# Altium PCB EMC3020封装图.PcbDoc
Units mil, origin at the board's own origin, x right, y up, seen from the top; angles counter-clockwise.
Board outline 6000 x 4000 mil, 2 copper layers (顶面, 底面), stack 12.7 mil thick; 1 components, 0 nets, 27 pads, 0 vias.
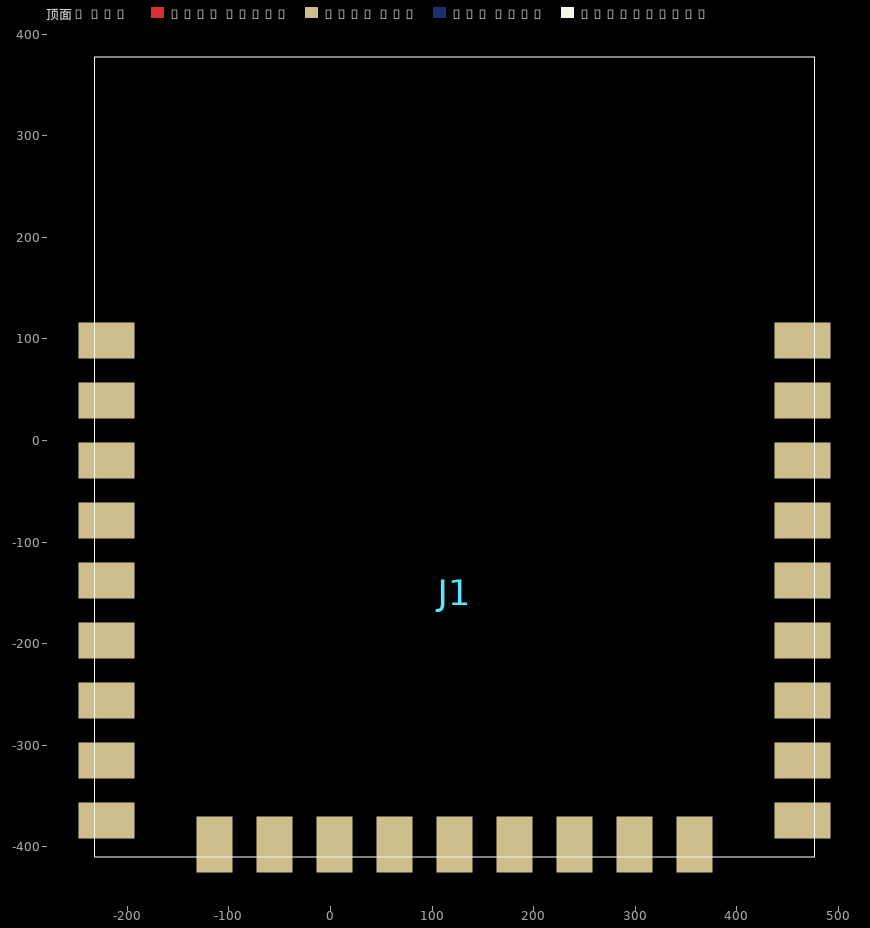
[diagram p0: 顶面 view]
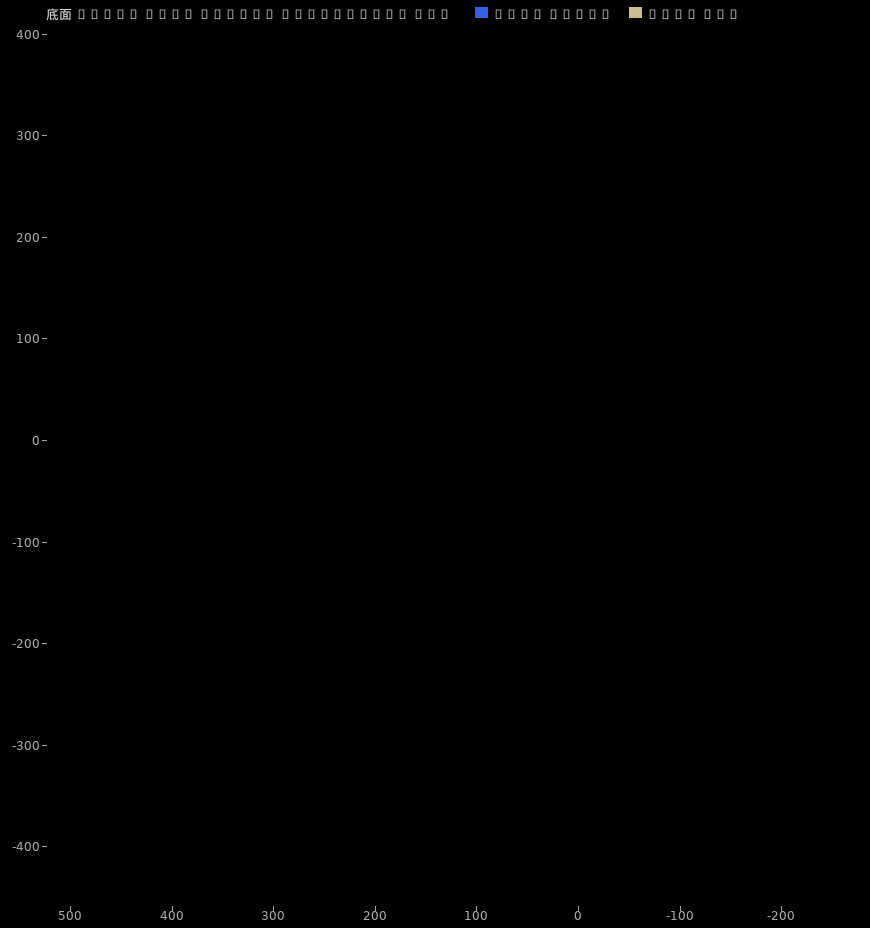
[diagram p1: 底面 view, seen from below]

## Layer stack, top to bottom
Top Solder: solder mask 0.4, Solder Resist, Dk 3.5
顶面: signal copper 1.35
Dielectric 1: dielectric 10, FR-4, Dk 4.3
底面: signal copper 1.35
Bottom Solder: solder mask 0.4, Solder Resist, Dk 3.5

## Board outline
-9000,-9000 -3000,-9000 -3000,-5000 -9000,-5000

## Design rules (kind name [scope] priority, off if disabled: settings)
Clearance "Clearance - Default - DEFAULT- SMD" [IsVia vs IsSMTPin] p1: gap=6 ignorepadtopadclearanceinfootprint=FALSE
Clearance "Clearance - Default - DEFAULT - Via" [IsVia vs IsVia] p2: gap=6 ignorepadtopadclearanceinfootprint=FALSE
Clearance "Clearance - Default - DEFAULT - Net" [All] p3: gap=6 ignorepadtopadclearanceinfootprint=FALSE except(0: Arc-Hole Track-Hole SMDPad-Hole THPad-Hole Via-Hole Fill-Hole Poly-Hole Region-Hole Text-Hole; 10: Text-Text)
ComponentClearance "ComponentClearance - Default - DEFAULT" [All] p1: gap=6 collisioncheckmode=3 verticalgap=10 showdistances=FALSE
FanoutControl Fanout_Small [(CompPinCount < 5)] p3: bgadir=Out bgaviamode=Centered fanoutstyle=Auto fanoutdirection=OutThenIn viagrid=1 // Fanout_Small (Default Rule)
FanoutControl Fanout_SOIC [IsSOIC] p4: bgadir=Out bgaviamode=Centered fanoutstyle=Auto fanoutdirection=Alternating viagrid=1 // Fanout_SOIC (Default Rule)
HoleToHoleClearance "HoleToHoleClearance - Default - DEFAULT" [All] p1: gap=6 allowstackedmicrovias=TRUE
Length "Default Length" [All] p1: maxlimit=50000 minlimit=0
MaxMinImpedance "Default Impedance" [All] p1: minimum=50.00 maximum=150.0
ParallelSegment "Default Parallel Segment Adjasent" [All] p1: limit=1000 gap=200
ParallelSegment "Default Parallel Segment Same Layer" [All] p2: limit=1000 gap=200
PlaneConnect "Default PlaneConnect" [All] p1: planeconnectstyle=Relief reliefexpansion=20 reliefentries=4 reliefconductorwidth=15 reliefairgap=10
PolygonConnect "PolygonConnect - Default SMT" [IsSMTPin] p1: connectstyle=Relief reliefconductorwidth=10 reliefentries=4 polygonreliefangle="45 Angle" airgapwidth=10
PolygonConnect "PolygonConnect - Default Pad" [All] p2: connectstyle=Relief reliefconductorwidth=15 reliefentries=4 polygonreliefangle="45 Angle" airgapwidth=10
RoutingLayers "RoutingLayers - Default - DEFAULT" [All] p1: top layer_v5=TRUE bottom layer_v5=TRUE
RoutingPriority "RoutingPriority - Default - DEFAULT" [All] p1: routingpriority=3
RoutingTopology "Default Routing Topology" [All] p1: topology=Shortest
RoutingVias "RoutingVias - Default - DEFAULT" [All] p1: holewidth=37 width=55 viastyle="Through Hole" minholewidth=37 minwidth=55 maxholewidth=37 maxwidth=55
SMDToCorner "SMDToCorner - Default - DEFAULT" [All] p1: distance=60000
SolderMaskExpansion [All] p1: expansion=4 istentingtop=FALSE
Width "Default Width" [All] p1: maxlimit=6 minlimit=6 preferedwidth=6
20 further rules are at their usual default settings.

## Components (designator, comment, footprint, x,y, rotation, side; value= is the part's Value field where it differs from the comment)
J1 "EMC3020-CORE" EMC3020-CORE -232.28,-409.45 r0 top

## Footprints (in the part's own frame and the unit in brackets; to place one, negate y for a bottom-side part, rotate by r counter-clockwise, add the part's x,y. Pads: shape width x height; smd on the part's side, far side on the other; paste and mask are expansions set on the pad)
EMC3020-CORE [mm]
  rect 1.4x0.9 smd: 1(0.3,12.9) 2(0.3,11.4) 3(0.3,9.9) 4(0.3,8.4) 5(0.3,6.9) 6(0.3,5.4) 7(0.3,3.9) 8(0.3,2.4) 9(0.3,0.9) 10(17.7,0.9) 11(17.7,2.4) 13(17.7,5.4) 14(17.7,6.9) 15(17.7,8.4) 16(17.7,9.9) 17(17.7,11.4) 18(17.7,12.9)
  rect 1.4x0.9 smd paste-0.1: 12(17.7,3.9)
  rect 0.9x1.4 smd: 19(3,0.3) 20(4.5,0.3) 21(6,0.3) 22(7.5,0.3) 23(9,0.3) 24(10.5,0.3) 25(12,0.3) 26(13.5,0.3) 27(15,0.3)
  顶面 pour cut-out: 0,20 18,20 18,14 0,14 0,20
  silkscreen extent 0,0 18,20

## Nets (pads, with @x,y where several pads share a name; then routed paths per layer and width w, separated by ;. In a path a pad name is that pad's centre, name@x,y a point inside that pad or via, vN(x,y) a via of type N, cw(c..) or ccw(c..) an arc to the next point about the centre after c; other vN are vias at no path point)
pads on no net: J1.1 J1.2 J1.3 J1.4 J1.5 J1.6 J1.7 J1.8 J1.9 J1.10 J1.11 J1.12 J1.13 J1.14 J1.15 J1.16 J1.17 J1.18 J1.19 J1.20 J1.21 J1.22 J1.23 J1.24 J1.25 J1.26 J1.27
